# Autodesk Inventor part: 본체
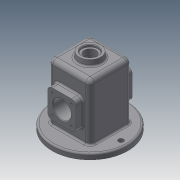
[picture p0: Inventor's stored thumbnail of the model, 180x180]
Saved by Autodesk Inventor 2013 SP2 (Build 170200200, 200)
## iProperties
Created: 2021-08
Part Number: 본체
Material: Generic
Document SubType Name: Modeling
Designer: kumcom8
Density: 1 g/cm^3
Author: kumcom8
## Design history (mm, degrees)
sketch "스케치1"
  geometry: C1 r 67 at (0, 0); 1 further point
  constraints: 1 centre point, 1 coincident
  dimensions: "d0" = 134 diameter of C1
extrude "돌출1" new body sketch "스케치1" distance "d1" = 10; taper "d2" = 0 deg
sketch "스케치2"
  geometry: L1 (-37, -37)-(37, -37); L2 (37, -37)-(37, 37); L3 (37, 37)-(-37, 37); L4 (-37, 37)-(-37, -37); L5 (-37, -37)-(37, 37); L6 (37, -37)-(-37, 37); C1 r 67 at (0, 0) reference
  constraints: 12 end point, 2 midpoint, 2 parallel, 1 horizontal, 1 perpendicular
  dimensions: "d3" = 74 distance of L2.end L3.end; "d5" = 74 distance of L1.end L2.end
extrude "돌출2" join sketch "스케치2" distance "d6" = 100; taper "d7" = 0 deg
sketch "스케치3"
  geometry: L1 (-25, 30)-(25, 30); L2 (25, 30)-(25, 80); L3 (25, 80)-(-25, 80); L4 (-25, 80)-(-25, 30); L5 (-25, 30)-(25, 80); L6 (25, 30)-(-25, 80); L7 (-67, 0)-(67, 0) reference; 3 further points
  constraints: 12 end point, 3 midpoint, 2 parallel, 1 horizontal, 1 perpendicular, 1 vertical alignment
  dimensions: "d8" = 50 distance of L3.end L2.end; "d9" = 50 distance of L2.end L1.end; "d10" = 55 distance from line of L7 point (0, 55)
extrude "돌출3" join sketch "스케치3" stored distance "d11" = 100; taper "d12" = 0 deg
sketch "스케치4"
  geometry: L1 (25, 80)-(-25, 80) reference; L2 (-67, 0)-(67, 0) reference; C1 r 16 at (0, 55); 2 further points
  constraints: 1 centre point, 1 midpoint, 1 vertical alignment
  dimensions: "d13" = 32 diameter of C1; "d14" = 55 distance from line of L2 C1.centre
extrude "돌출4" cut sketch "스케치4" distance "d15" = 110.75; taper "d16" = 0 deg
sketch "스케치5"
  geometry: C1 r 20 at (0, 0); 1 further point
  constraints: 1 centre point, 1 coincident
  dimensions: "d17" = 40 diameter of C1
extrude "돌출5" join sketch "스케치5" distance "d18" = 10; taper "d19" = 0 deg
sketch "스케치6"
  geometry: C1 r 20 at (0, 0) reference; C2 r 10.5 at (0, 0)
  constraints: 1 centre point, 1 coincident
  dimensions: "d20" = 21 diameter of C2
extrude "돌출6" cut sketch "스케치6" distance "d21" = 43.25; taper "d22" = 0 deg
sketch "스케치7"
  geometry: C1 r 10.5 at (0, 0) reference; C2 r 20 at (0, 0) reference; C3 r 14 at (0, 0)
  constraints: 1 centre point, 1 coincident
  dimensions: "d23" = 28 diameter of C3
extrude "돌출7" cut sketch "스케치7" distance "d24" = 4; taper "d25" = 0 deg
feature "면 기울기1" dims angle "d26" = 6 deg
sketch "스케치8"
  geometry: L1 (32, 32)-(-32, 32); L2 (-32, 32)-(-32, -32); L3 (-32, -32)-(32, -32); L4 (32, -32)-(32, 32); L5 (32, 32)-(-32, -32); L6 (-32, 32)-(32, -32); C1 r 67 at (0, 0) reference
  constraints: 12 end point, 2 midpoint, 2 parallel, 1 horizontal, 1 perpendicular
  dimensions: "d27" = 64 distance of L3.end L2.end; "d28" = 64 distance of L2.end L1.end
extrude "돌출8" cut sketch "스케치8" distance "d29" = 105; taper "d30" = 0 deg
sketch "스케치9"
  geometry: C1 r 16 at (32, 55) reference; C2 r 25 at (32, 55); 1 further point
  constraints: 1 centre point, 1 coincident
  dimensions: "d31" = 50 diameter of C2
extrude "돌출9" join sketch "스케치9" distance "d32" = 7; taper "d33" = 0 deg
feature "면 기울기2" dims angle "d34" = 20 deg
feature "면 기울기3" dims angle "d35" = 20 deg
sketch "스케치10"
  geometry: L1 (-17, 38)-(17, 38); L2 (17, 38)-(17, 72); L3 (17, 72)-(-17, 72); L4 (-17, 72)-(-17, 38); L5 (-17, 38)-(17, 72); L6 (17, 38)-(-17, 72); C1 r 16 at (0, 55) reference; 5 further points
  constraints: 12 end point, 4 coincident, 2 midpoint, 2 parallel, 1 horizontal, 1 perpendicular
  dimensions: "d36" = 34 distance of L3.end L2.end; "d37" = 34 distance of L2.end L1.end
hole "구멍1" sketch "스케치10" at (-17, 72), (-17, 38), (17, 38), (17, 72) diameter "d38" = 3.242; stored, may be unused: countersink angle "d42" = 90 deg, drill point angle "d44" = 118 deg; dims "d39" = 8, "d40" = 4, "d41" = 2, "d43" = 10
fillet "모깎기1" dims "d45" = 8
fillet "모깎기2" dims "d46" = 3
sketch "스케치11"
  geometry: C1 r 64 at (0, 0) reference; C2 r 4.5 at (-55, 0); C3 r 4.5 at (55, 0); A1 r 55 centre (0, 0) between (-55, 0) and (55, 0)
  constraints: 3 centre point, 2 point on circle, 1 coincident
  dimensions: "d47" = 110 diameter of A1; "d48" = 9 diameter of C2; "d49" = 9 diameter of C3
extrude "돌출10" cut sketch "스케치11" stored distance "d50" = 7; taper "d51" = 0 deg
node "작업 평면1"
sketch "스케치12"
  geometry: L1 (-37, 102)-(-37, 13) reference; L2 (29, 110)-(-29, 110) reference; L3 (18.949, 120)-(-18.949, 120) reference; 2 further points
  constraints: 1 other
  dimensions: "d53" = 37 distance from line of L1 point (0, 92); "d55" = 28 distance from line of point (0, 92) L3
feature "엠보싱1" sketch "스케치12" dims "d1" = 10, "d2" = 0, "d8" = 50, "d9" = 50, "d10" = 55, "d56" = 0.5, "d57" = 0
chamfer "모따기1" distance "d58" = 1; stored, may be unused: second distance "d59" = 2, angle "d60" = 45 deg
node "솔리드1"
mirror "대칭1"
mirror "대칭2"
other parameters: "d52" = 0
